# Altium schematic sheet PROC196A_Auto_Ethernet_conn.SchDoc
size 431 x 279 mm; Date: Not shown in title block; ApprovedBy: Not shown in title block; CheckedBy: Not shown in title block; Author: Not shown in title block; CompanyName: Not shown in title block; Engineer: Not shown in title block; Organization: Not shown in title block; Address1: Not shown in title block; Address2: Not shown in title block; Address3: Not shown in title block; Address4: Not shown in title block; DocumentNumber: 15; Revision: Use project parameter SCH_Rev; SheetNumber: 15; SheetTotal: 25; PageSetup: Record=PageOptions¦CenterHorizontal=True¦CenterVertical=True¦PrintScale=1.00¦XCorrection=1.00¦YCorrection=1.00¦PrintKind=0¦BorderSize=5000000¦LeftOffset=0¦BottomOffset=0¦Orientation=2¦PaperLength=1000¦PaperWidth=1000¦Scale=100¦PaperSource=15¦PrintQuality=600¦MediaType=1¦DitherType=10¦PaperKind=Letter¦PrintScaleMode=1
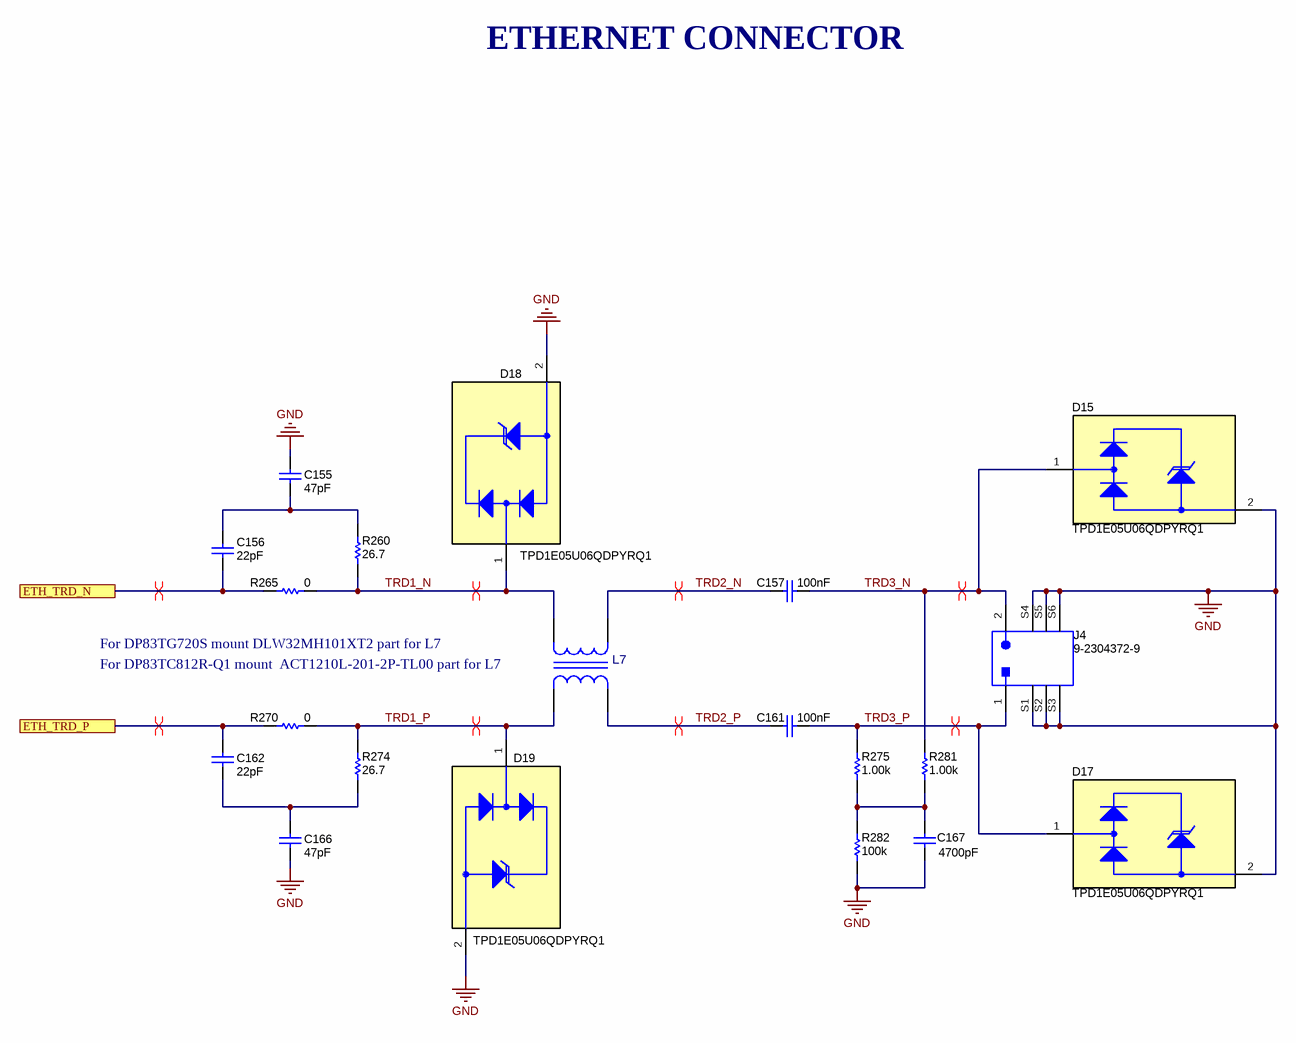
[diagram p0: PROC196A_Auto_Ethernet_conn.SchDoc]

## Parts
C155  ValueDisplayed: 47pF  [0402L]  (hidden comment: GRM1555C1H470FA01D)
C156  ValueDisplayed: 22pF  [0402L]  (hidden comment: GRM1555C1H220FA01D)
C157  Cap_F: 100nF  [0805_HV]  (hidden comment: CGA4J2X7R2A104K125AA)
C161  Cap_F: 100nF  [0805_HV]  (hidden comment: CGA4J2X7R2A104K125AA)
C162  ValueDisplayed: 22pF  [0402L]  (hidden comment: GRM1555C1H220FA01D)
C166  ValueDisplayed: 47pF  [0402L]  (hidden comment: GRM1555C1H470FA01D)
C167  ValueDisplayed: 4700pF  [1206L]  (hidden comment: GRM31BR73A472KW01L)
D15  TPD1E05U06QDPYRQ1  [DPY0002A]
D17  TPD1E05U06QDPYRQ1  [DPY0002A]
D18  TPD1E05U06QDPYRQ1  [DPY0002A]
D19  TPD1E05U06QDPYRQ1  [DPY0002A]
J4  9-2304372-9  [TE_9-2304372-9]
L7  ACT1210L-201-2P-TL00  [FP-ACT1210L-201-2P-TL00_SMD4-MFG]  (value not drawn)
R260  ValueDisplayed: 26.7  [0402L]  (hidden comment: CRCW040226R7FKED)
R265  ValueDisplayed: 0  [0402L]  (hidden comment: CRCW04020000Z0EDHP)
R270  ValueDisplayed: 0  [0402L]  (hidden comment: CRCW04020000Z0EDHP)
R274  ValueDisplayed: 26.7  [0402L]  (hidden comment: CRCW040226R7FKED)
R275  ValueDisplayed: 1.00k  [0805L]  (hidden comment: ERJ-P06F1001V)
R281  ValueDisplayed: 1.00k  [0805L]  (hidden comment: ERJ-P06F1001V)
R282  ValueDisplayed: 100k  [0805_HV]  (hidden comment: CRCW0805100KJNEA)

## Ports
ETH_TRD_N, ETH_TRD_P

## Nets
GND: C155.1 C166.2 C167.2 D15.2(GND) D17.2(GND) D18.2(GND) D19.2(GND) J4.S1(GND) J4.S2(GND) J4.S3(GND) J4.S4(GND) J4.S5(GND) J4.S6(GND) R282.1
ETH_TRD_N: C156.2 R265.1 ; port ETH_TRD_N
ETH_TRD_P: C162.1 R270.1 ; port ETH_TRD_P
TRD1_N: D18.1(I/O) L7.1 R260.1 R265.2
TRD1_P: D19.1(I/O) L7.2 R270.2 R274.2
TRD2_N: C157.2 L7.4
TRD2_P: C161.2 L7.3
TRD3_N: C157.1 D15.1(I/O) J4.2 R281.2
TRD3_P: C161.1 D17.1(I/O) J4.1 R275.2
NetC155_2: C155.2 C156.1 R260.2
NetC162_2: C162.2 C166.1 R274.1
NetC167_1: C167.1 R275.1 R281.1 R282.2

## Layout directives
differential pair: ETH_TRD_N, ETH_TRD_P, TRD1_N, TRD1_P, TRD2_N, TRD2_P, TRD3_N, TRD3_P

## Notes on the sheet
- ETHERNET CONNECTOR
- For DP83TG720S mount DLW32MH101XT2 part for L7
- For DP83TC812R-Q1 mount  ACT1210L-201-2P-TL00 part for L7

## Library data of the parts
C155 C166 = CMP-0006467-2: CAP, CERM, 47 pF, 50 V, +/- 1%, C0G/NP0, 0402; Manufacturer: MuRata; TaMin_C: -55°C; Polarized: N; SizeAreaWB_mm2: 3; Value1: Unknown; U/M: EA; Value: 47pF; TaMax_C: 125°C; SizeZ_mm: 0.6; SizeX_mm: 1; SizeY_mm: 0.5; Cap_Case: 0402; Value2: 50V; CompType: Capacitor; AEC Category: Q200
C156 C162 = CMP-0006438-2: CAP, CERM, 22 pF, 50 V, +/- 1%, C0G/NP0, 0402; Manufacturer: MuRata; TaMin_C: -55°C; Polarized: N; SizeAreaWB_mm2: 3; Value1: Unknown; U/M: EA; Value: 22pF; TaMax_C: 125°C; SizeZ_mm: 0.6; SizeX_mm: 1; SizeY_mm: 0.5; Cap_Case: 0402; Value2: 50V; CompType: Capacitor; AEC Category: Q200
C157 C161 = CMP-0007969-2: CAP, CERM, 0.1 uF, 100 V, +/- 10%, X7R, AEC-Q200 Grade 1, 0805; Manufacturer: TDK; TaMin_C: -55°C; ESR_ohm: 0.020726; Polarized: N; SizeAreaWB_mm2: 6.75; Value1: 0.020726 ohm; U/M: EA; Value: 0.1uF; TaMax_C: 125°C; SizeZ_mm: 1.45; SizeX_mm: 2; SizeY_mm: 1.25; Cap_Case: 0805; Value2: 100V; SizeArea_mm2: 2.5; AEC Qualified: Y; IRMS_A: 1.456A; AEC Grade: 1; AEC Category: Q200
C167 = CMP-0008920-2: CAP, CERM, 4700 pF, 1000 V, +/- 10%, X7R, 1206; Manufacturer: MuRata; TaMin_C: -55°C; Polarized: N; SizeAreaWB_mm2: 10.92; Value1: Unknown; U/M: EA; Value: 4700pF; TaMax_C: 125°C; SizeZ_mm: 1.35; SizeX_mm: 3.2; SizeY_mm: 1.6; Cap_Case: 1206; Value2: 1000V; SizeArea_mm2: 5.12; Cap_F: 4.7nF; VDC_V: 1kV; AEC Category: Q200
D15 D17-D19 = CMP-0073591-4: Automotive 1-Channel Ultra-Low-Capacitance IEC ESD Protection Diode, DPY0002A (X1SON-2); Alternate Manufacturer: Texas Instruments; Alternate PartNumber: TPD1E05U06QDPYTQ1; SizeZ_mm: 0.45; SizeAreaWB_mm2: 3.2; SizeArea_mm2: 0.6; CompType: IC; AEC Category: Q200; AEC Qualified: Y; SizeX_mm: 1.0
J4 = CMP-0078655-1: 1 Port Header Assembly, TH; Manufacturer: TE Connectivity; Gender: Male; CompType: Connector; Shrouded: Y
L7 = CMP-0089334-1: 200µH @ 100kHz 2 Line Common Mode Choke Surface Mount 70mA DCR 5.5Ohm; Manufacturer: TDK; Impedance At Frequency: 9.5kΩ @ 10MHz; Tolerance_%: -10/30%; SizeZ_mm: 2.5mm; DCR_ohm: 5.5; AEC Qualified: Yes; AEC Grade: Grade 1
R260 = CMP-0026210-2: RES, 26.7, 1%, 0.063 W, AEC-Q200 Grade 0, 0402; Manufacturer: Vishay-Dale; Power_W: 63mW; TempCo: 100 ppm/C; Value_Code: 26R7; Value: 26.7; SizeX_mm: 1; SizeY_mm: 0.5; SizeZ_mm: 0.6; Value2: 0.063W; AEC Qualified: Y; VDC_V: 50V; AEC Grade: 0; AEC Category: Q200; EIA_Code: E96
R265 R270 = CMP-0081856-1: RES, 0, 0%, 0.2 W, AEC-Q200 Grade 0, 0402; Manufacturer: Vishay-Dale; SizeAreaWB_mm2: 3; SizeArea_mm2: 0.5; AEC Qualified: Y; AEC Category: Q200; Value: 0; SizeZ_mm: 0.6; Power_W: 200mW; VDC_V: 50V; Value2: 0.2W; SizeX_mm: 1
R274 = CMP-0026210-2: RES, 26.7, 1%, 0.063 W, AEC-Q200 Grade 0, 0402; Manufacturer: Vishay-Dale; Power_W: 63mW; TempCo: 100 ppm/C; Value_Code: 26R7; Value: 26.7; SizeX_mm: 1; SizeY_mm: 0.5; SizeZ_mm: 0.6; Value2: 0.063W; CompType: Resistor; AEC Qualified: Y; VDC_V: 50V; AEC Grade: 0; AEC Category: Q200; EIA_Code: E96
R275 R281 = CMP-0021848-2: RES, 1.00 k, 1%, 0.25 W, 0805; Manufacturer: Panasonic; Power_W: 250mW; TempCo: 100 ppm/C; Value_Code: 1k00; U/M: EA; Value: 1.00k; EIA_Code: E96; Res_ohm: 1k; SizeX_mm: 2; SizeY_mm: 1.25; SizeZ_mm: 1.45; Value2: 0.25W; SizeArea_mm2: 2.5; VDC_V: 400V; AEC Category: Q200
R282 = CMP-0020444-3: RES, 100 k, 5%, 0.125 W, AEC-Q200 Grade 0, 0805; Manufacturer: Vishay-Dale; Power_W: 125mW; TempCo: 200 ppm/C; Value: 100k; EIA_Code: E24; SizeX_mm: 2; SizeY_mm: 1.25; SizeZ_mm: 1.45; Value2: 0.125W; SizeArea_mm2: 2.5; AEC Qualified: Y; VDC_V: 150V; AEC Category: Q200; AEC Grade: 0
